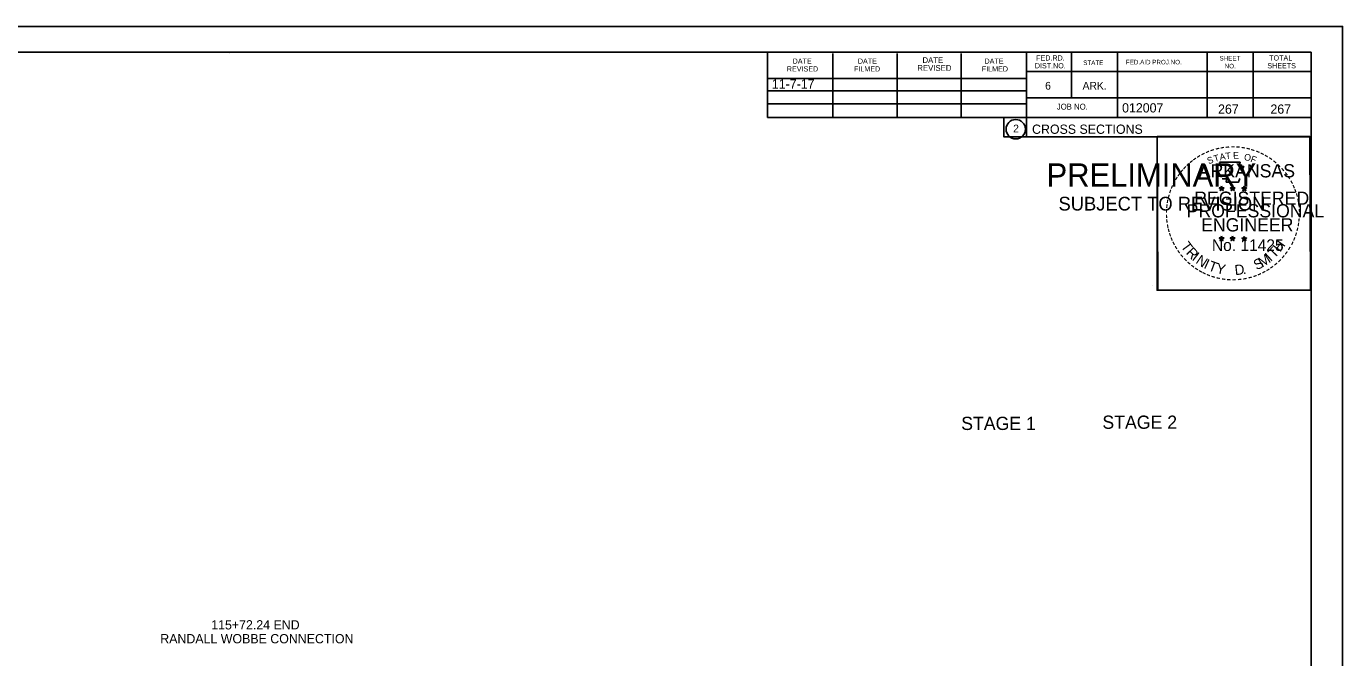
# Model space of a CAD drawing. Extents: x 1374311 to 1383814, y 384102 to 406278.
# Drawn here: x 1382684.6 to 1382883.8, y 388010.5 to 388106 of the extents above; entities that cross this region are included whole.
import ezdxf

# ---------------------------------------------------------------- set-up
doc = ezdxf.new("R2010")
doc.units = 0
for name, color, linetype in [('R_Axis Annot', 7, 'Continuous'), ('R_Border', 7, 'Continuous'), ('R_Border PE', 7, 'Continuous'), ('R_Border Prem', 7, 'Continuous'), ('R_Fin Surface', 7, 'Continuous'), ('R_No Plot', 7, 'Continuous'), ('R_Water', 7, 'Continuous')]:
    doc.layers.add(name, color=color, linetype=linetype)

msp = doc.modelspace()

# ---------------------------------------------------------------- linework, layer by layer
at = {"layer": 'R_Border'}
for p, q in [((1382562.86, 388102.07), (1382879.04, 388102.07)), ((1382715.38, 388101.81), (1382715.38, 388101.81)), ((1382715.38, 388101.81), (1382715.38, 388101.81)), ((1382796.78, 388092.19), (1382796.78, 388102.07)), ((1382806.64, 388092.19), (1382806.64, 388101.87)), ((1382816.4, 388092.19), (1382816.4, 388101.87)), ((1382826.08, 388092.19), (1382826.08, 388101.87)), ((1382835.94, 388102.07), (1382835.94, 388089.27)), ((1382842.78, 388102.07), (1382842.78, 388095.13)), ((1382849.72, 388102.07), (1382849.72, 388092.19)), ((1382863.3, 388102.07), (1382863.3, 388092.19)), ((1382870.24, 388102.07), (1382870.24, 388092.19)), ((1382879.04, 387896.61), (1382879.04, 388102.07)), ((1382796.78, 388098.05), (1382835.94, 388098.05)), ((1382879.04, 388099.13), (1382835.94, 388099.13)), ((1382879.04, 388099.15), (1382879.04, 388099.15)), ((1382796.78, 388096.19), (1382835.94, 388096.19)), ((1382796.78, 388092.19), (1382796.78, 388094.25)), ((1382796.78, 388094.25), (1382835.94, 388094.25)), ((1382879.04, 388095.13), (1382835.94, 388095.13)), ((1382838.9, 388095.13), (1382879.04, 388095.13)), ((1382879.04, 388092.19), (1382796.78, 388092.19)), ((1382835.94, 388089.27), (1382879.04, 388089.27))]:
    msp.add_line(p, q, dxfattribs=at)
msp.add_circle((1382834.33, 388090.4), 1.47, dxfattribs=at)
at = {"layer": 'R_Border PE'}
for p, q in [((1382865.13, 388081.52), (1382865.47, 388081.41)), ((1382865.13, 388081.52), (1382865.38, 388081.48)), ((1382865.13, 388081.52), (1382865.36, 388081.4)), ((1382865.47, 388081.78), (1382865.43, 388081.52)), ((1382865.47, 388081.41), (1382865.47, 388081.78)), ((1382865.47, 388081.78), (1382865.52, 388081.53)), ((1382865.82, 388081.52), (1382865.47, 388081.41)), ((1382865.82, 388081.52), (1382865.54, 388081.47)), ((1382865.82, 388081.52), (1382865.62, 388081.42)), ((1382866.8, 388081.52), (1382867.14, 388081.41)), ((1382866.8, 388081.52), (1382867.05, 388081.48)), ((1382866.8, 388081.52), (1382867.03, 388081.4)), ((1382867.14, 388081.78), (1382867.1, 388081.52)), ((1382867.14, 388081.41), (1382867.14, 388081.78)), ((1382867.14, 388081.78), (1382867.19, 388081.53)), ((1382867.49, 388081.52), (1382867.14, 388081.41)), ((1382867.49, 388081.52), (1382867.21, 388081.47)), ((1382867.49, 388081.52), (1382867.29, 388081.42)), ((1382868.56, 388081.51), (1382868.91, 388081.4)), ((1382868.56, 388081.51), (1382868.81, 388081.46)), ((1382868.56, 388081.51), (1382868.8, 388081.39)), ((1382868.91, 388081.76), (1382868.87, 388081.51)), ((1382868.91, 388081.4), (1382868.91, 388081.76)), ((1382868.91, 388081.76), (1382868.96, 388081.51)), ((1382869.26, 388081.51), (1382868.91, 388081.4)), ((1382869.26, 388081.51), (1382868.97, 388081.46)), ((1382869.26, 388081.51), (1382869.05, 388081.41)), ((1382865.26, 388081.11), (1382865.47, 388081.41)), ((1382865.26, 388081.11), (1382865.38, 388081.36)), ((1382865.26, 388081.11), (1382865.47, 388081.33)), ((1382865.69, 388081.11), (1382865.47, 388081.41)), ((1382865.69, 388081.11), (1382865.47, 388081.33)), ((1382865.69, 388081.11), (1382865.55, 388081.4)), ((1382866.93, 388081.11), (1382867.14, 388081.41)), ((1382866.93, 388081.11), (1382867.05, 388081.36)), ((1382866.93, 388081.11), (1382867.14, 388081.33)), ((1382867.36, 388081.11), (1382867.14, 388081.41)), ((1382867.36, 388081.11), (1382867.14, 388081.33)), ((1382867.36, 388081.11), (1382867.22, 388081.4)), ((1382868.69, 388081.1), (1382868.91, 388081.4)), ((1382868.69, 388081.1), (1382868.82, 388081.35)), ((1382868.69, 388081.1), (1382868.91, 388081.32)), ((1382869.12, 388081.1), (1382868.91, 388081.4)), ((1382869.12, 388081.1), (1382868.91, 388081.32)), ((1382869.12, 388081.1), (1382868.98, 388081.39)), ((1382865.12, 388073.95), (1382865.47, 388073.84)), ((1382865.12, 388073.95), (1382865.37, 388073.9)), ((1382865.12, 388073.95), (1382865.36, 388073.83)), ((1382865.25, 388073.54), (1382865.47, 388073.84)), ((1382865.25, 388073.54), (1382865.38, 388073.78)), ((1382865.25, 388073.54), (1382865.47, 388073.76)), ((1382865.47, 388074.2), (1382865.43, 388073.95)), ((1382865.47, 388073.84), (1382865.47, 388074.2)), ((1382865.47, 388074.2), (1382865.52, 388073.95)), ((1382865.82, 388073.95), (1382865.47, 388073.84)), ((1382865.68, 388073.54), (1382865.47, 388073.84)), ((1382865.68, 388073.54), (1382865.47, 388073.75)), ((1382865.82, 388073.95), (1382865.53, 388073.9)), ((1382865.68, 388073.54), (1382865.55, 388073.83)), ((1382865.82, 388073.95), (1382865.61, 388073.85)), ((1382866.79, 388073.95), (1382867.14, 388073.84)), ((1382866.79, 388073.95), (1382867.04, 388073.9)), ((1382866.79, 388073.95), (1382867.03, 388073.83)), ((1382866.92, 388073.54), (1382867.14, 388073.84)), ((1382866.92, 388073.54), (1382867.05, 388073.78)), ((1382866.92, 388073.54), (1382867.14, 388073.76)), ((1382867.14, 388074.2), (1382867.1, 388073.95)), ((1382867.14, 388073.84), (1382867.14, 388074.2)), ((1382867.14, 388074.2), (1382867.19, 388073.95)), ((1382867.49, 388073.95), (1382867.14, 388073.84)), ((1382867.35, 388073.54), (1382867.14, 388073.84)), ((1382867.35, 388073.54), (1382867.14, 388073.75)), ((1382867.49, 388073.95), (1382867.2, 388073.9)), ((1382867.35, 388073.54), (1382867.22, 388073.83)), ((1382867.49, 388073.95), (1382867.28, 388073.85)), ((1382868.56, 388073.94), (1382868.91, 388073.83)), ((1382868.56, 388073.94), (1382868.81, 388073.89)), ((1382868.56, 388073.94), (1382868.79, 388073.82)), ((1382868.69, 388073.53), (1382868.91, 388073.83)), ((1382868.69, 388073.53), (1382868.82, 388073.77)), ((1382868.69, 388073.53), (1382868.9, 388073.75)), ((1382868.91, 388074.19), (1382868.87, 388073.94)), ((1382869.12, 388073.53), (1382868.9, 388073.74)), ((1382868.91, 388073.83), (1382868.91, 388074.19)), ((1382868.91, 388074.19), (1382868.96, 388073.94)), ((1382869.25, 388073.94), (1382868.91, 388073.83)), ((1382869.12, 388073.53), (1382868.91, 388073.83)), ((1382869.25, 388073.94), (1382868.97, 388073.89)), ((1382869.12, 388073.53), (1382868.98, 388073.82)), ((1382869.25, 388073.94), (1382869.05, 388073.84))]:
    msp.add_line(p, q, dxfattribs=at)
for points in [[(1382865.17, 388085.4), (1382865.44, 388084.57)], [(1382868.68, 388084.48), (1382868.82, 388084.76), (1382868.13, 388084.74), (1382868.28, 388085.4), (1382865.17, 388085.4)], [(1382865.47, 388081.78), (1382865.69, 388081.11), (1382865.13, 388081.52), (1382865.82, 388081.52), (1382865.26, 388081.11), (1382865.47, 388081.78)], [(1382865.66, 388082.98), (1382865.66, 388082.89), (1382866.22, 388082.87), (1382866.17, 388082.4), (1382868.04, 388082.4), (1382868.24, 388082.93)], [(1382867.14, 388081.78), (1382867.36, 388081.11), (1382866.8, 388081.52), (1382867.49, 388081.52), (1382866.93, 388081.11), (1382867.14, 388081.78)], [(1382868.91, 388081.76), (1382869.12, 388081.1), (1382868.56, 388081.51), (1382869.26, 388081.51), (1382868.69, 388081.1), (1382868.91, 388081.76)], [(1382865.47, 388074.2), (1382865.68, 388073.54), (1382865.12, 388073.95), (1382865.82, 388073.95), (1382865.25, 388073.54), (1382865.47, 388074.2)], [(1382867.14, 388074.2), (1382867.35, 388073.54), (1382866.79, 388073.95), (1382867.49, 388073.95), (1382866.92, 388073.54), (1382867.14, 388074.2)], [(1382868.91, 388074.19), (1382869.12, 388073.53), (1382868.56, 388073.94), (1382869.25, 388073.94), (1382868.69, 388073.53), (1382868.91, 388074.19)]]:
    msp.add_lwpolyline(points, dxfattribs=at)
for centre, radius in [((1382865.47, 388081.41), 0.172), ((1382865.47, 388081.41), 0.145), ((1382865.47, 388081.41), 0.116), ((1382865.47, 388081.41), 0.0991), ((1382867.14, 388081.41), 0.172), ((1382867.14, 388081.41), 0.145), ((1382867.14, 388081.41), 0.116), ((1382867.14, 388081.41), 0.0991), ((1382868.91, 388081.4), 0.172), ((1382868.91, 388081.4), 0.145), ((1382868.91, 388081.4), 0.116), ((1382868.91, 388081.4), 0.0991), ((1382865.47, 388081.41), 0.0747), ((1382865.47, 388081.41), 0.0495), ((1382865.47, 388081.41), 0.0296), ((1382867.14, 388081.41), 0.0747), ((1382867.14, 388081.41), 0.0495), ((1382867.14, 388081.41), 0.0296), ((1382868.91, 388081.4), 0.0747), ((1382868.91, 388081.4), 0.0495), ((1382868.91, 388081.4), 0.0296), ((1382865.47, 388073.84), 0.172), ((1382865.47, 388073.84), 0.145), ((1382865.47, 388073.84), 0.116), ((1382865.47, 388073.84), 0.0991), ((1382865.47, 388073.84), 0.0747), ((1382865.47, 388073.84), 0.0495), ((1382865.47, 388073.84), 0.0296), ((1382867.14, 388073.84), 0.172), ((1382867.14, 388073.84), 0.145), ((1382867.14, 388073.84), 0.116), ((1382867.14, 388073.84), 0.0991), ((1382867.14, 388073.84), 0.0747), ((1382867.14, 388073.84), 0.0495), ((1382867.14, 388073.84), 0.0296), ((1382868.91, 388073.83), 0.172), ((1382868.91, 388073.83), 0.145), ((1382868.91, 388073.83), 0.116), ((1382868.91, 388073.83), 0.0991), ((1382868.91, 388073.83), 0.0747), ((1382868.91, 388073.83), 0.0495), ((1382868.91, 388073.83), 0.0296)]:
    msp.add_circle(centre, radius, dxfattribs=at)
at = {"layer": 'R_No Plot'}
for p, q in [((1382550.46, 388105.96), (1382883.79, 388105.96)), ((1382855.08, 388066.81), (1382855.08, 388066.81))]:
    msp.add_line(p, q, dxfattribs=at)
for points in [[(1382550.45, 388105.96), (1382883.79, 388105.96), (1382883.79, 387892.62), (1382550.45, 387892.62)], [(1382796.78, 388102.07), (1382796.78, 388092.19), (1382832.51, 388092.19), (1382832.51, 388089.27), (1382855.71, 388089.27), (1382855.71, 388066.05), (1382879.04, 388066.05), (1382879.04, 387896.61), (1382562.86, 387896.61), (1382562.86, 388102.07)], [(1382855.71, 388089.3), (1382878.81, 388089.3), (1382878.93, 388066.05), (1382855.83, 388066.05)]]:
    msp.add_lwpolyline(points, close=True, dxfattribs=at)

# ---------------------------------------------------------------- texts
at = {"layer": 'R_Axis Annot'}
for s, p in [('115+72.24 END', (1382712.61, 388014.73)), ('RANDALL WOBBE CONNECTION', (1382704.9, 388012.63))]:
    msp.add_text(s, height=1.4, dxfattribs=at).set_placement(p)
at = {"layer": 'R_Border'}
for s, height, p in [('FED.RD.', 0.782, (1382837.42, 388100.79)), ('SHEET', 0.684, (1382865.16, 388100.79)), ('TOTAL', 0.782, (1382872.68, 388100.79)), ('REVISED', 0.782, (1382799.7, 388099.13)), ('DATE', 0.782, (1382800.58, 388100.31)), ('FILMED', 0.782, (1382809.86, 388099.13)), ('DATE', 0.782, (1382810.44, 388100.31)), ('REVISED', 0.879, (1382819.44, 388099.23)), ('DATE', 0.879, (1382820.22, 388100.41)), ('FILMED', 0.782, (1382829.2, 388099.13)), ('DATE', 0.782, (1382829.6, 388100.31)), ('DIST.NO.', 0.782, (1382837.22, 388099.61)), ('STATE', 0.684, (1382844.54, 388100.11)), ('FED.AID PROJ.NO.', 0.684, (1382851, 388100.21)), ('NO.', 0.684, (1382865.94, 388099.61)), ('SHEETS', 0.782, (1382872.4, 388099.61)), ('6', 1.17, (1382838.78, 388096.39)), ('ARK.', 1.172, (1382844.44, 388096.39)), ('JOB NO.', 0.879, (1382840.54, 388093.37)), ('012007', 1.4, (1382850.42, 388092.93)), ('2', 1.17, (1382833.94, 388089.92)), ('CROSS SECTIONS', 1.4, (1382836.8, 388089.7))]:
    msp.add_text(s, height=height, rotation=360, dxfattribs=at).set_placement(p)
at = {"layer": 'R_Border PE'}
for s, height, rotation, p in [('-', 1.6, 13.6301, (1382864.66, 388086.77)), ('-', 1.6, 10.2193, (1382865.34, 388086.93)), ('-', 1.6, 5.8968, (1382866.07, 388087.04)), ('-', 1.6, 0.1862, (1382866.84, 388087.11)), ('-', 1.6, 357.743, (1382867.57, 388087.1)), ('-', 1.6, 352.1617, (1382868.31, 388087.04)), ('-', 1.6, 347.2049, (1382869.03, 388086.93)), ('-', 1.6, 38.9507, (1382861, 388084.8)), ('-', 1.6, 36.2317, (1382861.47, 388085.18)), ('-', 1.6, 34.0636, (1382862.05, 388085.57)), ('-', 1.6, 28.7918, (1382862.65, 388085.94)), ('-', 1.6, 24.3072, (1382863.28, 388086.26)), ('S', 1, 21.594, (1382863.52, 388085.08)), ('-', 1.6, 19.1761, (1382863.91, 388086.53)), ('T', 1, 16.4036, (1382864.44, 388085.41)), ('A', 1, 11.2132, (1382865.26, 388085.66)), ('T', 1, 6.0228, (1382866.11, 388085.83)), ('E', 1, 0.8323, (1382867.22, 388085.94)), ('O', 1, 350.4515, (1382868.82, 388085.73)), ('F', 1, 340.0707, (1382869.77, 388085.5)), ('-', 1.6, 342.3362, (1382869.66, 388086.77)), ('-', 1.6, 337.8551, (1382870.4, 388086.55)), ('-', 1.6, 334.1211, (1382871.03, 388086.28)), ('-', 1.6, 329.6409, (1382871.61, 388086)), ('-', 1.6, 325.8627, (1382872.25, 388085.64)), ('-', 1.6, 320.5297, (1382872.86, 388085.21)), ('-', 1.6, 54.2325, (1382859.3, 388082.85)), ('-', 1.6, 50.6142, (1382859.71, 388083.42)), ('-', 1.6, 48.423, (1382860.12, 388083.9)), ('-', 1.6, 42.9622, (1382860.56, 388084.38)), ('ARKANSAS', 2, 360, (1382862.02, 388083.11)), ('-', 1.6, 315.5786, (1382873.46, 388084.72)), ('-', 1.6, 309.8797, (1382874.03, 388084.17)), ('-', 1.6, 306.6522, (1382874.56, 388083.57)), ('-', 1.6, 67.7743, (1382858.4, 388081.1)), ('-', 1.6, 62.8713, (1382858.66, 388081.71)), ('-', 1.6, 58.0706, (1382858.97, 388082.32)), ('-', 1.4, 303.6753, (1382875.04, 388083)), ('-', 1.6, 299.6684, (1382875.36, 388082.39)), ('-', 1.6, 294.6628, (1382875.68, 388081.78)), ('-', 1.6, 81.2013, (1382857.85, 388079.04)), ('-', 1.6, 75.461, (1382857.99, 388079.75)), ('-', 1.6, 72.3945, (1382858.18, 388080.47)), ('REGISTERED', 2, 360, (1382861.34, 388078.96)), ('DWB', 0.01, 360, (1382865.46, 388081.41)), ('DWB', 0.01, 360, (1382867.13, 388081.41)), ('DWB', 0.01, 360, (1382868.9, 388081.39)), ('-', 1.6, 290.5728, (1382875.94, 388081.21)), ('-', 1.6, 285.1233, (1382876.18, 388080.63)), ('-', 1.6, 280.5493, (1382876.38, 388079.88)), ('-', 1.6, 89.0622, (1382857.75, 388077.65)), ('-', 1.6, 85.1863, (1382857.78, 388078.35)), ('PROFESSIONAL', 2, 360, (1382860.19, 388077.06)), ('-', 1.6, 276.5962, (1382876.54, 388079.12)), ('-', 1.6, 274.3301, (1382876.6, 388078.39)), ('-', 1.6, 269.9407, (1382876.63, 388077.76)), ('-', 1.6, 94.1959, (1382857.79, 388076.92)), ('-', 1.6, 98.9479, (1382857.86, 388076.26)), ('-', 1.6, 101.7149, (1382858, 388075.52)), ('ENGINEER', 2, 360, (1382862.38, 388074.93)), ('-', 1.6, 255.7626, (1382876.43, 388075.76)), ('-', 1.6, 260.9953, (1382876.54, 388076.44)), ('-', 1.6, 263.5172, (1382876.61, 388077.1)), ('-', 1.6, 105.4578, (1382858.16, 388074.93)), ('-', 1.6, 109.0874, (1382858.37, 388074.3)), ('-', 1.6, 114.0643, (1382858.63, 388073.7)), ('T', 1.54, 306.0406, (1382859.23, 388072.68)), ('No. 11425', 1.757, 360, (1382864.01, 388071.98)), ('DWB', 0.01, 360, (1382865.46, 388073.83)), ('DWB', 0.01, 360, (1382867.13, 388073.83)), ('DWB', 0.01, 360, (1382868.89, 388073.82)), ('H', 1.54, 54.6088, (1382874.35, 388071.71)), ('-', 1.6, 247.8887, (1382876.03, 388074.37)), ('-', 1.6, 252.8681, (1382876.25, 388075.04)), ('-', 1.6, 115.7289, (1382858.93, 388073.08)), ('-', 1.6, 120.4471, (1382859.29, 388072.5)), ('-', 1.6, 125.8934, (1382859.69, 388071.94)), ('R', 1.54, 314.005, (1382859.99, 388071.63)), ('I', 1.54, 321.9694, (1382860.89, 388070.7)), ('M', 1.54, 32.6563, (1382871.61, 388069.44)), ('I', 1.54, 42.1136, (1382872.9, 388070.29)), ('T', 1.54, 46.6444, (1382873.46, 388070.77)), ('-', 1.6, 233.8452, (1382874.97, 388072.34)), ('-', 1.6, 239.0712, (1382875.37, 388072.99)), ('-', 1.6, 244.6197, (1382875.77, 388073.74)), ('-', 1.6, 130.7181, (1382860.15, 388071.38)), ('-', 1.6, 134.2238, (1382860.67, 388070.84)), ('-', 1.6, 138.9338, (1382861.2, 388070.38)), ('-', 1.6, 144.6463, (1382861.75, 388069.97)), ('N', 1.54, 326.5002, (1382861.46, 388070.22)), ('I', 1.54, 335.3603, (1382862.67, 388069.44)), ('T', 1.54, 339.8912, (1382863.33, 388069.11)), ('Y', 1.54, 347.8556, (1382864.55, 388068.67)), ('D', 1.54, 6.3969, (1382867.53, 388068.31)), ('S', 1.54, 26.9312, (1382870.78, 388069.04)), ('-', 1.6, 215.7363, (1382872.99, 388070.23)), ('-', 1.6, 221.0851, (1382873.54, 388070.7)), ('-', 1.6, 225.7653, (1382874.06, 388071.21)), ('-', 1.6, 231.2538, (1382874.54, 388071.77)), ('-', 1.6, 148.0898, (1382862.31, 388069.6)), ('-', 1.6, 151.5704, (1382862.89, 388069.27)), ('-', 1.6, 154.6002, (1382863.41, 388069.03)), ('-', 1.6, 158.5612, (1382864.04, 388068.77)), ('-', 1.6, 162.7983, (1382864.72, 388068.56)), ('-', 1.6, 167.5555, (1382865.44, 388068.4)), ('-', 1.6, 173.1155, (1382866.21, 388068.29)), ('-', 1.6, 176.5183, (1382866.96, 388068.23)), ('-', 1.6, 181.5918, (1382867.7, 388068.25)), ('-', 1.6, 185.8167, (1382868.51, 388068.33)), ('-', 1.6, 191.2858, (1382869.25, 388068.46)), ('.', 1.54, 13.7642, (1382868.72, 388068.43)), ('-', 1.6, 195.4743, (1382869.98, 388068.66)), ('-', 1.6, 200.7184, (1382870.65, 388068.9)), ('-', 1.6, 204.2516, (1382871.27, 388069.17)), ('-', 1.6, 207.3568, (1382871.9, 388069.49)), ('-', 1.6, 212.2491, (1382872.46, 388069.84))]:
    msp.add_text(s, height=height, rotation=rotation, dxfattribs=at).set_placement(p)
at = {"layer": 'R_Border Prem'}
for s, height, p in [('PRELIMINARY', 3.5, (1382838.99, 388081.73)), ('DWB', 0.01, (1382839.74, 388083.58)), ('SUBJECT TO REVISION', 2.0751, (1382840.8, 388078.1))]:
    msp.add_text(s, height=height, rotation=360, dxfattribs=at).set_placement(p)
at = {"layer": 'R_Fin Surface'}
msp.add_text('11-7-17', height=1.4, dxfattribs=at).set_placement((1382797.43, 388096.55))
at = {"layer": 'R_Water'}
for p in [(1382864.94, 388092.74), (1382872.86, 388092.74)]:
    msp.add_text('267', height=1.4, rotation=360, dxfattribs=at).set_placement(p)
for s, p in [('STAGE 1', (1382826.08, 388044.9)), ('STAGE 2', (1382847.44, 388045.08))]:
    msp.add_text(s, height=2, dxfattribs=at).set_placement(p)

doc.saveas('drawing.dxf')
